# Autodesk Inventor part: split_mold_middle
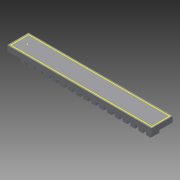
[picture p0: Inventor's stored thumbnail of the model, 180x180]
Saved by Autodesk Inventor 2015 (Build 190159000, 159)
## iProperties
Created: 2015-04
Part Number: split_mold_middle
Material: Generic
Document SubType Name: Modeling
Designer: sungeun
Density: 1 g/cm^3
Appearance: Default
Author: sungeun
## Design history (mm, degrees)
sketch "Sketch1"
  geometry: L1 (-4, -7.5)-(4, -7.5); L2 (4, -7.5)-(4, 7.5); L3 (4, 7.5)-(-4, 7.5); L4 (-4, 7.5)-(-4, -7.5); L5 (-4, -7.5)-(4, 7.5); L6 (4, -7.5)-(-4, 7.5); 1 further point
  constraints: 12 end point, 2 midpoint, 2 parallel, 1 horizontal, 1 perpendicular
  dimensions: "d0" = 8 distance of L3.end L2.end; "d1" = 15 distance of L2.end L1.end
extrude "Extrusion1" new body sketch "Sketch1" distance "d2" = 15; taper "d3" = 0 deg
sketch "Sketch2"
  geometry: L1 (-3, 5.5)-(3, 5.5); L2 (3, 5.5)-(3, -5.5); L3 (3, -5.5)-(-3, -5.5); L4 (-3, -5.5)-(-3, 5.5); L5 (4, -7.5)-(4, 7.5) reference; L6 (-4, 7.5)-(-4, -7.5) reference; L7 (4, 7.5)-(-4, 7.5) reference; L8 (-4, -7.5)-(4, -7.5) reference; 1 further point
  constraints: 8 end point, 2 parallel, 1 horizontal, 1 perpendicular
  dimensions: "d4" = 1 distance between parallel lines of L5 L2; "d5" = 1 distance between parallel lines of L6 L4; "d6" = 2 distance between parallel lines of L7 L1; "d7" = 2 distance between parallel lines of L8 L3
extrude "Extrusion2" cut sketch "Sketch2" distance "d8" = 13; taper "d9" = 0 deg
sketch "Sketch3"
  geometry: L1 (0, 15)-(-15, 15) reference; L2 (-15, 0)-(-12, 0); L3 (-12, 0)-(-12, 15); L4 (-12, 15)-(-15, 15); L5 (-15, 15)-(-15, 0); L6 (-15, 0)-(-15, 15) reference; 2 further points
  constraints: 8 end point, 2 midpoint, 2 parallel, 1 coincident, 1 horizontal, 1 perpendicular, 1 point on line
  dimensions: "d17" = 3 distance of L2.start L2.end; "d18" = 15 distance of L2.end L3.end
extrude "Extrusion3" join sketch "Sketch3" distance "d11" = 2; taper "d12" = 0 deg
pattern_linear "Rectangular Pattern1"
sketch "Sketch4"
  geometry: L1 (0, 15)-(-12, 15); L2 (-12, 15)-(-12, 0); L3 (-12, 0)-(0, 0); L4 (0, 0)-(0, 15); 1 further point
  constraints: 8 end point, 2 parallel, 1 horizontal, 1 perpendicular
extrude "Extrusion4" join sketch "Sketch4" distance "d19" = 2; taper "d20" = 0 deg
sketch "Sketch5"
  geometry: 1 further point
sketch "Sketch6"
  geometry: L1 (0, 0)-(15, 0); L2 (15, 0)-(15, 15); L3 (15, 15)-(0, 15); L4 (0, 15)-(0, 0); 1 further point
  constraints: 8 end point, 2 parallel, 1 horizontal, 1 perpendicular
  dimensions: "d21" = 15 distance of L3.end L1.start; "d22" = 15 distance of L2.end L3.end
extrude "Extrusion5" join sketch "Sketch6" distance "d23" = 2; taper "d24" = 0 deg
sketch "Sketch7"
  geometry: 1 further point
sketch "Sketch8"
  geometry: L1 (3, 5.5)-(3, -5.5) reference; L2 (157, -5.5)-(157, 5.5) reference; L3 (3, 1)-(157, 1); L4 (157, 1)-(157, -1); L5 (157, -1)-(3, -1); L6 (3, -1)-(3, 1); 3 further points
  constraints: 8 end point, 2 midpoint, 2 parallel, 2 point on line, 1 coincident, 1 horizontal, 1 perpendicular
  dimensions: "d25" = 2 distance between parallel lines of L5 L3
extrude "Extrusion6" cut sketch "Sketch8" distance "d26" = 2; taper "d27" = 0 deg
sketch "Sketch9"
  geometry: L1 (-3, 5.5)-(163, 5.5); L2 (163, 5.5)-(163, -5.5); L3 (163, -5.5)-(-3, -5.5); L4 (-3, -5.5)-(-3, 5.5); L5 (164, 6.5)-(-4, 6.5); L6 (-4, 6.5)-(-4, -6.5); L7 (-4, -6.5)-(164, -6.5); L8 (164, -6.5)-(164, 6.5)
  constraints: 16 end point, 4 parallel, 2 perpendicular, 1 horizontal, 3 other
  dimensions: "d29" = 1 distance between parallel lines of L1 L5
extrude "Extrusion7" join sketch "Sketch9" distance "d30" = 2; taper "d31" = 0 deg
sketch "Sketch10"
  geometry: L1 (-3, 5.5)-(163, 5.5) reference; L2 (7, 5.5)-(3, 5.5); L3 (3, 5.5)-(3, 1); L4 (3, 1)-(7, 1); L5 (7, 1)-(7, 5.5); L6 (163, -5.5)-(-3, -5.5) reference; L7 (7, -1)-(3, -1); L8 (3, -1)-(3, -5.5); L9 (3, -5.5)-(7, -5.5); L10 (7, -5.5)-(7, -1); L11 (6, 4.5)-(4, 4.5); L12 (4, 4.5)-(4, 2); L13 (4, 2)-(6, 2); L14 (6, 2)-(6, 4.5); L15 (6, -2)-(4, -2); L16 (4, -2)-(4, -4.5); L17 (4, -4.5)-(6, -4.5); L18 (6, -4.5)-(6, -2); 3 further points
  constraints: 32 end point, 8 parallel, 4 perpendicular, 2 horizontal, 2 midpoint, 2 point on line, 1 vertical alignment, 6 other
  dimensions: "d32" = 4 distance between parallel lines of L3 L5; "d33" = 4 distance between parallel lines of L8 L10; "d34" = 4.5 distance of L7.end L8.end; "d35" = 1 distance between parallel lines of L5 L14; "d36" = 1 distance between parallel lines of L10 L18
extrude "Extrusion8" join sketch "Sketch10" distance "d37" = 2; taper "d38" = 0 deg
pattern_linear "Rectangular Pattern2" dims "d41" = 10
sketch "Sketch11"
  geometry: L1 (10, -11.5)-(-170, -11.5); L2 (-170, -11.5)-(-170, 11.5); L3 (-170, 11.5)-(10, 11.5); L4 (10, 11.5)-(10, -11.5); L5 (-156, 7.5)-(-166, 7.5) reference; L6 (-116, -7.5)-(-124, -7.5) reference; L7 (-166, -7.5)-(-166, 7.5) reference; L8 (6, 7.5)-(6, -7.5) reference; 1 further point
  constraints: 8 end point, 2 parallel, 1 horizontal, 1 perpendicular
  dimensions: "d42" = 4 distance between parallel lines of L3 L5; "d43" = 4 distance between parallel lines of L6 L1; "d44" = 4 distance between parallel lines of L2 L7; "d45" = 4 distance between parallel lines of L4 L8
extrude "Extrusion9" new body sketch "Sketch11" distance "d46" = 21; taper "d47" = 0 deg
combine "Combine1"
  body "Solid1"
sketch "Sketch13"
  geometry: L1 (6, 7.5)-(6, -7.5) reference; L2 (6, -7.5)-(-4, -7.5) reference; L3 (-4, -7.5)-(-4, 7.5) reference; L4 (-4, 7.5)-(6, 7.5) reference; L5 (-166, -7.5)-(-166, 7.5) reference; L6 (-166, 7.5)-(-156, 7.5) reference; L7 (-156, 7.5)-(-156, -7.5) reference; L8 (-156, -7.5)-(-166, -7.5) reference; L9 (-154, -7.5)-(-154, 7.5) reference; L10 (-154, 7.5)-(-146, 7.5) reference; L11 (-146, 7.5)-(-146, -7.5) reference; L12 (-146, -7.5)-(-154, -7.5) reference; L13 (-144, -7.5)-(-144, 7.5) reference; L14 (-144, 7.5)-(-136, 7.5) reference; L15 (-136, 7.5)-(-136, -7.5) reference; L16 (-136, -7.5)-(-144, -7.5) reference; L17 (-134, -7.5)-(-134, 7.5) reference; L18 (-134, 7.5)-(-126, 7.5) reference; L19 (-126, 7.5)-(-126, -7.5) reference; L20 (-126, -7.5)-(-134, -7.5) reference; L21 (-124, -7.5)-(-124, 7.5) reference; L22 (-124, 7.5)-(-116, 7.5) reference; L23 (-116, 7.5)-(-116, -7.5) reference; L24 (-116, -7.5)-(-124, -7.5) reference; L25 (-114, -7.5)-(-114, 7.5) reference; L26 (-114, 7.5)-(-106, 7.5) reference; L27 (-106, 7.5)-(-106, -7.5) reference; L28 (-106, -7.5)-(-114, -7.5) reference; L29 (-104, -7.5)-(-104, 7.5) reference; L30 (-104, 7.5)-(-96, 7.5) reference; L31 (-96, 7.5)-(-96, -7.5) reference; L32 (-96, -7.5)-(-104, -7.5) reference; L33 (-94, -7.5)-(-94, 7.5) reference; L34 (-94, 7.5)-(-86, 7.5) reference; L35 (-86, 7.5)-(-86, -7.5) reference; L36 (-86, -7.5)-(-94, -7.5) reference; L37 (-84, -7.5)-(-84, 7.5) reference; L38 (-84, 7.5)-(-76, 7.5) reference; L39 (-76, 7.5)-(-76, -7.5) reference; L40 (-76, -7.5)-(-84, -7.5) reference; L41 (-74, -7.5)-(-74, 7.5) reference; L42 (-74, 7.5)-(-66, 7.5) reference; L43 (-66, 7.5)-(-66, -7.5) reference; L44 (-66, -7.5)-(-74, -7.5) reference; L45 (-64, -7.5)-(-64, 7.5) reference; L46 (-64, 7.5)-(-56, 7.5) reference; L47 (-56, 7.5)-(-56, -7.5) reference; L48 (-56, -7.5)-(-64, -7.5) reference; L49 (-54, -7.5)-(-54, 7.5) reference; L50 (-54, 7.5)-(-46, 7.5) reference; L51 (-46, 7.5)-(-46, -7.5) reference; L52 (-46, -7.5)-(-54, -7.5) reference; L53 (-44, -7.5)-(-44, 7.5) reference; L54 (-44, 7.5)-(-36, 7.5) reference; L55 (-36, 7.5)-(-36, -7.5) reference; L56 (-36, -7.5)-(-44, -7.5) reference; L57 (-34, -7.5)-(-34, 7.5) reference; L58 (-34, 7.5)-(-26, 7.5) reference; L59 (-26, 7.5)-(-26, -7.5) reference; L60 (-26, -7.5)-(-34, -7.5) reference; L61 (-24, -7.5)-(-24, 7.5) reference; L62 (-24, 7.5)-(-16, 7.5) reference; L63 (-16, 7.5)-(-16, -7.5) reference; L64 (-16, -7.5)-(-24, -7.5) reference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; 2 further points
extrude "Extrusion10" cut sketch "Sketch13" distance "d48" = 13; taper "d49" = 0 deg
sketch "Sketch14"
  geometry: L1 (10, -11.5)-(-170, -11.5) reference; L2 (10, 11.5)-(10, -11.5) reference; L3 (-170, 11.5)-(10, 11.5) reference; L4 (-170, -11.5)-(-170, 11.5) reference; L5 (-166, -7.5)-(6, -7.5) reference; L6 (-166, 7.5)-(-166, -7.5) reference; L7 (6, 7.5)-(-166, 7.5) reference; L8 (6, -7.5)-(6, 7.5) reference; 1 further point
extrude "Extrusion11" cut sketch "Sketch14" distance "d50" = 2; taper "d51" = 0 deg
sketch "Sketch15"
  geometry: L1 (-10, -11.5)-(170, -11.5) reference; L2 (170, -11.5)-(170, 11.5) reference; L3 (170, 11.5)-(-10, 11.5) reference; L4 (-10, 11.5)-(-10, -11.5) reference; 1 further point
  node "Projected Loop3"
sketch "Sketch16"
  geometry: L1 (-10, 11.5)-(-10, -11.5) reference; L2 (170, 11.5)-(-10, 11.5) reference; L3 (-10, -11.5)-(170, -11.5) reference; L4 (170, -11.5)-(170, 11.5) reference; L5 (-12, 13.5)-(-12, -13.5); L6 (-12, -13.5)-(172, -13.5); L7 (172, -13.5)-(172, 13.5); L8 (172, 13.5)-(-12, 13.5); 1 further point
  constraints: 8 end point, 3 other
  dimensions: "d52" = 2 distance between parallel lines of L2 L8
extrude "Extrusion12" join sketch "Sketch16" distance "d53" = 7; taper "d54" = 0 deg
body "Solid2"
node "Projected Loop1"
node "Projected Loop2"
